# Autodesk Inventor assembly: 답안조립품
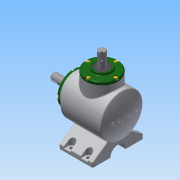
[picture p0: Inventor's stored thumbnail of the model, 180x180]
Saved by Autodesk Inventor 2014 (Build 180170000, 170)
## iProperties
Created: 2017-04
Part Number: 답안조립품
Document SubType Name: Assembly
Designer: SCD-A12
Author: SCD-A12
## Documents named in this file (14)
- C:\Users\SCD-A12\Desktop\470408V1014\답안조립품.iam
- C:\Users\SCD-A12\Desktop\470408V1014\본체.ipt
- C:\Users\SCD-A12\Desktop\470408V1014\메인 베벨기어.ipt
- C:\Users\SCD-A12\Desktop\470408V1014\메인 축.ipt
- 메인 축.ipt
- C:\Users\SCD-A12\Desktop\470408V1014\베어링 6203.ipt
- C:\Users\SCD-A12\Desktop\470408V1014\볼트 M4.ipt
- C:\Users\SCD-A12\Desktop\470408V1014\서브 베벨기어.ipt
- C:\Users\SCD-A12\Desktop\470408V1014\서브 축.ipt
- 서브 축.ipt
- C:\Users\SCD-A12\Desktop\470408V1014\오일실 17 32 8.ipt
- C:\Users\SCD-A12\Desktop\470408V1014\커버.ipt
- C:\Users\SCD-A12\Desktop\470408V1014\키 4x4.ipt
- C:\Users\SCD-A12\Desktop\470408V1014\키 5x5.ipt
## Named parameters: d11_d10 = 0
